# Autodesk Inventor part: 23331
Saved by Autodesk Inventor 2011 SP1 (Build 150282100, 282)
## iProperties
Created: 2012-04
Part Number: 23331
Checked By: TraceParts S.A.
Catalog Web Link: www.traceparts.com
Document SubType Name: Modeling
Designer: TraceParts
Density: 1 g/cm^3
Company: TraceParts S.A.
Author: TraceParts
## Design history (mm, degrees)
feature "23331"
node "Solide1"
